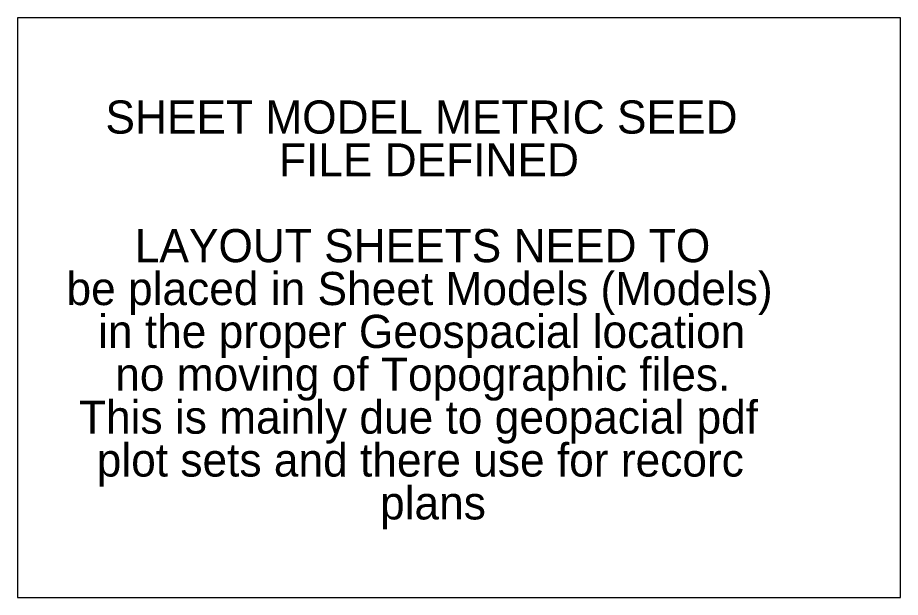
# Model space of a CAD drawing. Extents: x 0 to 0.813, y 0 to 0.533.
import ezdxf

# ---------------------------------------------------------------- set-up
doc = ezdxf.new("R2010")
doc.units = 0
doc.layers.add('Default', color=7, linetype='Continuous')

msp = doc.modelspace()

# ---------------------------------------------------------------- linework, layer by layer
at = {"layer": 'Default'}
msp.add_lwpolyline([(0, 0), (0.8128, 0), (0.8128, 0.5334), (0, 0.5334)], close=True, dxfattribs=at)

# ---------------------------------------------------------------- texts
for s, height, p in [('SHEET MODEL METRIC SEED', 0.0304801, (0.08084, 0.42672)), ('FILE DEFINED', 0.0304801, (0.24058, 0.38727)), ('LAYOUT SHEETS NEED TO', 0.0304801, (0.10784, 0.30838)), ('be placed in Sheet Models (Models)', 0.0304801, (0.04498, 0.26893)), ('in the proper Geospacial location', 0.0304801, (0.07406, 0.22948)), ('no moving of Topographic files. ', 0.0304801, (0.08985, 0.19004)), ('This is mainly due to geopacial pdf', 0.0304801, (0.05648, 0.15059)), ('plot sets and there use for recorc', 0.0304801, (0.07282, 0.11114)), ('plans', 0.03048, (0.33371, 0.07169))]:
    msp.add_text(s, height=height, dxfattribs=at).set_placement(p)

doc.saveas('drawing.dxf')
